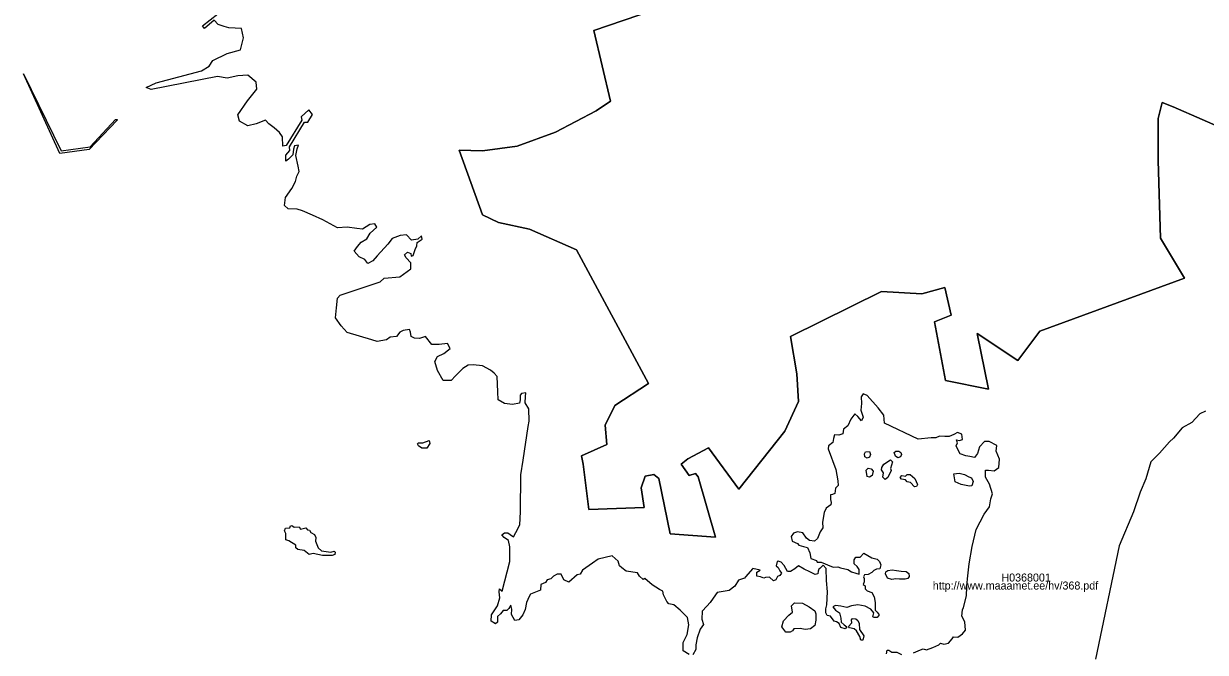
# Model space of a CAD drawing. Extents: x 369010 to 739155, y 6377141 to 6634081.
# Drawn here: x 428377 to 432069, y 6515270 to 6517234 of the extents above; entities that cross this region are included whole.
import ezdxf

# ---------------------------------------------------------------- set-up
doc = ezdxf.new("R2010")
doc.units = 0
for name, color, linetype in [('H_LINK', 7, 'Continuous'), ('H_PIIR', 7, 'Continuous'), ('H_TUNNUS', 7, 'Continuous')]:
    doc.layers.add(name, color=color, linetype=linetype)

msp = doc.modelspace()

# ---------------------------------------------------------------- linework, layer by layer
at = {"layer": 'H_PIIR'}
for points in [[(430456.38, 6515263.5646), (430437.5299, 6515275.0946), (430437.5299, 6515301.2847), (430450.09, 6515326.4346), (430455.3299, 6515356.8247), (430451.14, 6515378.8346), (430428.1, 6515401.8846), (430408.2101, 6515418.6546), (430392.4999, 6515421.7947), (430386.2201, 6515429.1346), (430375.7399, 6515450.0947), (430373.65, 6515461.6247), (430363.1801, 6515466.8647), (430341.1901, 6515481.5346), (430318.1501, 6515501.4447), (430312.9201, 6515498.2946), (430301.4001, 6515508.7746), (430295.1101, 6515519.2546), (430259.51, 6515524.4947), (430245.8999, 6515533.9247), (430238.5701, 6515540.2147), (430234.3799, 6515554.8846), (430215.53, 6515571.6546), (430171.5501, 6515561.1746), (430154.7999, 6515548.5946), (430123.38, 6515527.6346), (430116.0499, 6515515.0646), (430106.63, 6515512.9647), (430080.4501, 6515489.9147), (430064.7399, 6515497.2446), (430056.36, 6515515.0646), (430043.8, 6515515.0646), (430032.28, 6515508.7746), (430023.9001, 6515500.3947), (430012.3801, 6515497.2446), (430007.6699, 6515488.3447), (429993.01, 6515482.0546), (429991.96, 6515464.2346), (429960.55, 6515451.6646), (429956.3601, 6515445.3746), (429947.98, 6515426.5147), (429943.8, 6515404.5047), (429936.47, 6515387.7447), (429923.8999, 6515372.0246), (429911.3401, 6515369.9247), (429900.8599, 6515388.7846), (429901.91, 6515405.5546), (429898.77, 6515418.1346), (429892.49, 6515407.6546), (429887.25, 6515401.3646), (429875.73, 6515401.3646), (429867.3599, 6515390.8846), (429857.93, 6515382.5046), (429857.93, 6515364.6847), (429851.65, 6515359.4446), (429838.0299, 6515367.8346), (429839.08, 6515387.7447), (429857.93, 6515416.0347), (429865.2601, 6515441.1846), (429863.17, 6515459.0046), (429864.21, 6515468.4346), (429872.5899, 6515461.0947), (429895.6299, 6515554.3646), (429895.6299, 6515600.4646), (429891.44, 6515619.3347), (429878.87, 6515628.7646), (429871.5401, 6515637.1447), (429879.92, 6515643.4347), (429890.39, 6515643.4347), (429896.68, 6515638.1947), (429907.15, 6515630.8547), (429914.48, 6515644.4846), (429927.04, 6515668.5846), (429929.1399, 6515709.4546), (429930.18, 6515824.7247), (429937.51, 6515870.8347), (429953.22, 6515975.6246), (429956.3601, 6515992.3946), (429955.32, 6516031.1647), (429943.8, 6516050.0246), (429944.8401, 6516069.9347), (429945.8899, 6516081.4647), (429932.28, 6516079.3646), (429928.0901, 6516074.1246), (429928.0901, 6516059.4547), (429926, 6516048.9747), (429904, 6516044.7846), (429879.92, 6516047.9247), (429860.0201, 6516059.4547), (429858.98, 6516084.6046), (429856.88, 6516131.7646), (429847.46, 6516142.2446), (429835.94, 6516151.6747), (429810.8099, 6516165.2946), (429781.4899, 6516168.4447), (429765.78, 6516167.3947), (429749.03, 6516156.9147), (429735.4101, 6516143.2946), (429725.99, 6516133.8647), (429712.3801, 6516119.1846), (429688.29, 6516119.1846), (429670.49, 6516150.6247), (429662.1101, 6516178.9247), (429670.49, 6516194.6346), (429690.3901, 6516204.0646), (429709.24, 6516219.7847), (429701.9001, 6516235.5047), (429675.73, 6516232.3646), (429652.69, 6516232.3646), (429632.79, 6516257.5146), (429613.94, 6516251.2246), (429598.24, 6516252.2747), (429587.77, 6516257.5146), (429585.67, 6516270.0847), (429582.5301, 6516278.4746), (429562.64, 6516275.3247), (429552.16, 6516270.0847), (429541.69, 6516257.5146), (429522.84, 6516255.4146), (429511.32, 6516247.0347), (429481.9999, 6516241.7947), (429465.2499, 6516247.0347), (429387.76, 6516269.0447), (429368.9099, 6516290.0046), (429351.1101, 6516315.1447), (429354.25, 6516346.5846), (429357.3999, 6516376.9746), (429365.77, 6516386.4046), (429491.43, 6516427.2746), (429504.0001, 6516438.8046), (429552.16, 6516442.9946), (429586.72, 6516468.1446), (429586.72, 6516487.0047), (429572.0601, 6516502.7247), (429566.8199, 6516512.1546), (429576.25, 6516520.5447), (429586.72, 6516516.3447), (429587.77, 6516507.9646), (429594.0501, 6516510.0647), (429600.3299, 6516528.9246), (429605.5701, 6516540.4546), (429606.6199, 6516550.9346), (429622.3201, 6516561.4047), (429620.23, 6516571.8847), (429608.71, 6516561.4047), (429588.8201, 6516558.2646), (429573.1099, 6516575.0346), (429553.21, 6516572.9347), (429528.08, 6516563.5046), (429515.5099, 6516545.6946), (429481.9999, 6516509.0147), (429468.39, 6516493.2947), (429452.6801, 6516484.9146), (429443.26, 6516497.4847), (429425.4599, 6516505.8746), (429409.75, 6516523.6846), (429420.2199, 6516538.3547), (429432.04, 6516551.3846), (429449.54, 6516562.4546), (429460.2401, 6516579.5946), (429480.9601, 6516598.0846), (429474.68, 6516608.5646), (429458.9699, 6516606.4747), (429435.9301, 6516591.8046), (429418.13, 6516593.8946), (429387.76, 6516598.0846), (429357.3999, 6516595.9947), (429312.3699, 6516621.1446), (429279.91, 6516635.8147), (429248.4901, 6516649.4346), (429231.7401, 6516654.6746), (429203.4601, 6516655.7246), (429191.9401, 6516666.2046), (429195.09, 6516691.3547), (429214.9801, 6516719.6447), (429226.5001, 6516741.6546), (429230.69, 6516757.3746), (429238.0201, 6516772.0447), (429234.88, 6516788.8047), (429227.5499, 6516822.3447), (429231.7401, 6516843.3046), (429235.93, 6516854.8246), (429223.36, 6516852.7347), (429220.2201, 6516842.2546), (429218.12, 6516824.4347), (429204.5099, 6516810.8147), (429196.14, 6516804.5246), (429196.14, 6516823.3947), (429208.7, 6516838.0646), (429207.65, 6516849.5846), (429254.7801, 6516926.0847), (429265.25, 6516926.0847), (429279.91, 6516950.1846), (429268.39, 6516964.8647), (429244.2999, 6516942.8547), (429246.4, 6516932.3747), (429197.18, 6516853.7846), (429186.7101, 6516851.6847), (429185.66, 6516881.0247), (429176.83, 6516894.32), (429159.7395, 6516908.8848), (429143.203, 6516920.7911), (429133.2811, 6516932.6973), (429104.1768, 6516921.4525), (429077.7185, 6516914.8379), (429051.9215, 6516929.39), (429046.6299, 6516949.8953), (429076.3955, 6516993.5516), (429105.4998, 6517029.2704), (429104.1768, 6517051.7601), (429077.7185, 6517072.9268), (429046.3899, 6517071.7446), (429013.35, 6517063.73), (428983.33, 6517069.31), (428775.31, 6517028.51), (428760.67, 6517034.47), (428791.9399, 6517049.7446), (428932.8588, 6517086.8174), (428956.6713, 6517101.3695), (428968.9, 6517118.9047), (429012.8954, 6517141.0571), (429054.5674, 6517152.3019), (429063.97, 6517189.58), (429057.9099, 6517219.5046), (429017.91, 6517221.65), (429003.46, 6517225.7946), (428984.6099, 6517232.0746), (428973.0899, 6517244.6547), (428942.72, 6517219.5046), (428936.44, 6517227.8847), (428983.5601, 6517264.5646)], [(432149.14, 6516895.15), (431967.8001, 6516974.8599), (431933.5599, 6516987.79), (431921.16, 6516938.19), (431921.16, 6516806.75), (431928.6, 6516563.71), (432002.9601, 6516439.71), (431551.86, 6516273.55), (431482.4601, 6516181.79), (431356.0499, 6516266.11), (431390.7501, 6516092.51), (431256.9101, 6516119.7899), (431222.2099, 6516303.3099), (431274.2601, 6516323.15), (431254.4299, 6516409.95), (431183.3, 6516390.32), (431057.53, 6516397.9299), (430772.5, 6516256.5699), (430792.3299, 6516140.0099), (430797.33, 6516053.5099), (430755.2, 6515961.8101), (430611.6, 6515780.6601), (430516.22, 6515909.66), (430451.73, 6515875.2701), (430430.99, 6515858.1), (430456.0601, 6515822.7099), (430475.98, 6515829.0499), (430484.51, 6515818.7901), (430538.9799, 6515629.9699), (430397.37, 6515640.86), (430361.05, 6515813.34), (430346.2999, 6515825.82), (430319.3001, 6515820.6), (430306.5901, 6515784.29), (430315.6699, 6515722.56), (430143.1899, 6515717.1199), (430125.03, 6515858.73), (430120.01, 6515884.63), (430199.36, 6515919.4), (430194.0199, 6515980.3701), (430224.0901, 6516041.85), (430328.79, 6516109.9799), (430104.6099, 6516527.3501), (429957.82, 6516592.72), (429860.4699, 6516612.93), (429810.8799, 6516636.8299), (429737.41, 6516838.99), (429810.8799, 6516837.1501), (429919.25, 6516851.85), (430038.59, 6516895.4501), (430165.33, 6516961.6099), (430210.37, 6516992.2199), (430158.1, 6517213.2901), (430345.07, 6517275.91)], [(430345.07, 6517275.91), (430158.1, 6517213.2901), (430210.37, 6516992.2199), (430165.33, 6516961.6099), (430038.59, 6516895.4501), (429919.25, 6516851.85), (429810.8799, 6516837.1501), (429737.41, 6516838.99), (429810.8799, 6516636.8299), (429860.4699, 6516612.93), (429957.82, 6516592.72), (430104.6099, 6516527.3501), (430328.79, 6516109.9799), (430224.0901, 6516041.85), (430194.0199, 6515980.3701), (430199.36, 6515919.4), (430120.01, 6515884.63), (430125.03, 6515858.73), (430143.1899, 6515717.1199), (430315.6699, 6515722.56), (430306.5901, 6515784.29), (430319.3001, 6515820.6), (430346.2999, 6515825.82), (430361.05, 6515813.34), (430397.37, 6515640.86), (430538.9799, 6515629.9699), (430484.51, 6515818.7901), (430475.98, 6515829.0499), (430456.0601, 6515822.7099), (430430.99, 6515858.1), (430451.73, 6515875.2701), (430516.22, 6515909.66), (430611.6, 6515780.6601), (430755.2, 6515961.8101), (430797.33, 6516053.5099), (430792.3299, 6516140.0099), (430772.5, 6516256.5699), (431057.53, 6516397.9299), (431183.3, 6516390.32), (431254.4299, 6516409.95), (431274.2601, 6516323.15), (431222.2099, 6516303.3099), (431256.9101, 6516119.7899), (431390.7501, 6516092.51), (431356.0499, 6516266.11), (431482.4601, 6516181.79), (431551.86, 6516273.55), (432002.9601, 6516439.71), (431928.6, 6516563.71), (431921.16, 6516806.75), (431921.16, 6516938.19), (431933.5599, 6516987.79), (431967.8001, 6516974.8599), (432149.14, 6516895.15)], [(431157.44, 6515269.4146), (431178.3499, 6515278.5646), (431187.4999, 6515281.1847), (431197.9499, 6515278.5646), (431217.5599, 6515285.1047), (431235.85, 6515294.2646), (431241.08, 6515299.4947), (431251.5399, 6515295.5747), (431265.91, 6515299.4947), (431277.6701, 6515312.5746), (431281.5899, 6515319.1147), (431295.9699, 6515317.8046), (431310.35, 6515328.2646), (431319.49, 6515340.0347), (431316.8801, 6515366.1946), (431307.7301, 6515383.1947), (431310.35, 6515402.8147), (431312.96, 6515410.6646), (431322.1101, 6515447.2847), (431323.42, 6515474.7446), (431326.0299, 6515499.5946), (431331.2599, 6515546.6746), (431339.75, 6515600.9546), (431352.82, 6515654.5746), (431377.65, 6515701.6647), (431394.6399, 6515725.2046), (431398.56, 6515750.0546), (431403.79, 6515765.7447), (431394.6399, 6515795.8247), (431381.5701, 6515818.0546), (431381.5701, 6515838.9847), (431390.7201, 6515838.9847), (431409.02, 6515837.6746), (431423.39, 6515848.1346), (431426.0001, 6515874.2947), (431415.5501, 6515899.1447), (431416.86, 6515916.1446), (431393.33, 6515929.2246), (431378.96, 6515929.2246), (431363.28, 6515912.2247), (431356.7401, 6515891.2946), (431347.59, 6515879.5247), (431333.22, 6515882.1446), (431320.1, 6515883.8046), (431302.4701, 6515890.2146), (431295.14, 6515903.8446), (431289.9, 6515915.3646), (431294.09, 6515924.8046), (431290.9501, 6515934.2347), (431300.38, 6515932.1346), (431309.8, 6515935.2846), (431307.7101, 6515952.0447), (431294.09, 6515957.2847), (431282.57, 6515950.9947), (431267.9101, 6515944.7147), (431255.35, 6515944.7147), (431238.59, 6515945.7547), (431227.08, 6515940.5147), (431212.4201, 6515940.5147), (431171.58, 6515936.3246), (431066.86, 6515986.6246), (431064.7701, 6516011.7746), (431046.97, 6516033.7846), (431012.41, 6516072.5546), (430999.84, 6516077.7946), (430993.56, 6516068.3646), (430994.61, 6516047.4047), (430992.5099, 6516026.4446), (430999.84, 6516005.4846), (430994.61, 6515993.9646), (430983.09, 6516007.5847), (430973.6601, 6516015.9646), (430961.1, 6515999.2046), (430951.6801, 6515978.2447), (430938.06, 6515967.7647), (430935.9699, 6515953.0946), (430923.4001, 6515948.9046), (430909.79, 6515949.9547), (430906.6501, 6515938.4247), (430904.55, 6515925.8446), (430891.99, 6515915.3646), (430890.9399, 6515905.9347), (430913.98, 6515842.0147), (430920.26, 6515806.3846), (430921.31, 6515791.7147), (430912.9299, 6515783.3346), (430910.84, 6515766.5646), (430903.51, 6515763.4247), (430897.22, 6515762.3747), (430897.22, 6515747.7046), (430899.32, 6515738.2746), (430898.27, 6515730.9346), (430884.6599, 6515720.4546), (430878.3801, 6515706.8347), (430873.1399, 6515677.4947), (430874.1899, 6515659.6747), (430865.81, 6515647.1046), (430857.43, 6515626.1447), (430848.01, 6515617.7646), (430832.3001, 6515619.8547), (430822.3499, 6515626.6647), (430810.8299, 6515643.4347), (430795.13, 6515646.5746), (430782.5599, 6515642.3847), (430775.23, 6515631.9047), (430778.37, 6515617.2346), (430795.13, 6515610.9446), (430799.3201, 6515605.7046), (430812.93, 6515601.5146), (430825.49, 6515598.3747), (430832.8201, 6515581.6046), (430835.97, 6515563.7947), (430853.77, 6515557.5047), (430855.8601, 6515552.2647), (430868.4299, 6515552.2647), (430900.8901, 6515538.6446), (430907.1699, 6515536.5446), (430920.78, 6515537.5946), (430929.1601, 6515534.4547), (430952.2001, 6515529.2147), (430963.7199, 6515521.8746), (430977.33, 6515517.6847), (430986.7599, 6515514.5446), (430986.7599, 6515529.2147), (430981.5199, 6515538.6446), (430972.1, 6515547.0247), (430972.1, 6515559.6046), (430977.33, 6515567.9847), (430989.9, 6515567.9847), (431001.42, 6515580.5547), (431026.5499, 6515565.8846), (431043.2999, 6515561.6946), (431050.63, 6515554.3646), (431054.8199, 6515543.8846), (431051.68, 6515531.3046), (431041.21, 6515530.2546), (431032.83, 6515526.0646), (431026.5499, 6515519.7846), (431015.0299, 6515513.4946), (431003.5099, 6515512.4447), (431000.37, 6515506.1547), (431002.4601, 6515500.9147), (431002.4601, 6515490.4346), (430999.32, 6515482.0546), (431005.6, 6515477.8647), (431005.6, 6515468.4346), (431011.89, 6515462.1446), (431026.5499, 6515456.9046), (431033.88, 6515444.3247), (431037.0201, 6515426.5147), (431037.0201, 6515412.8946), (431037.0201, 6515402.4147), (431043.2999, 6515396.1246), (431049.58, 6515387.7447), (431043.2999, 6515379.3546), (431033.88, 6515379.3546), (431029.69, 6515381.4547), (431032.83, 6515394.0246), (431023.4, 6515405.5546), (431005.6, 6515414.9847), (430983.61, 6515419.1846), (430963.7199, 6515416.0347), (430949.06, 6515410.7946), (430930.2099, 6515414.9847), (430913.4599, 6515417.0846), (430905.08, 6515412.8946), (430913.4599, 6515402.4147), (430926.02, 6515394.0246), (430930.2099, 6515377.2646), (430931.26, 6515364.6847), (430940.6801, 6515356.3046), (430949.06, 6515350.0146), (430943.82, 6515343.7246), (430930.2099, 6515347.9246), (430924.9699, 6515360.4946), (430916.6, 6515365.7346), (430909.27, 6515367.8346), (430897.75, 6515383.5546), (430887.28, 6515385.6447), (430883.09, 6515394.0246), (430883.09, 6515406.6046), (430886.23, 6515419.1846), (430888.32, 6515459.0046), (430885.1799, 6515494.6247), (430884.1301, 6515532.3546), (430874.71, 6515542.8346), (430864.24, 6515532.3546), (430861.1001, 6515530.2546), (430859, 6515523.9747), (430857.96, 6515515.5846), (430849.5801, 6515513.4946), (430832.8201, 6515521.8746), (430815.02, 6515530.2546), (430798.27, 6515540.7347), (430786.75, 6515531.3046), (430773.14, 6515522.9247), (430763.71, 6515522.9247), (430753.2401, 6515541.7846), (430743.8199, 6515552.2647), (430734.39, 6515555.4046), (430731.2501, 6515554.3646), (430728.11, 6515540.7347), (430734.39, 6515535.4947), (430739.63, 6515525.0246), (430744.86, 6515517.6847), (430739.63, 6515510.3446), (430732.2999, 6515507.2047), (430727.0599, 6515496.7246), (430719.7301, 6515493.5847), (430707.17, 6515505.1047), (430694.6, 6515504.0646), (430689.36, 6515501.9646), (430678.89, 6515506.1547), (430667.38, 6515508.2546), (430667.38, 6515520.8246), (430677.85, 6515527.1146), (430654.81, 6515532.3546), (430631.77, 6515506.1547), (430628.6301, 6515501.9646), (430610.83, 6515495.6747), (430599.31, 6515476.8147), (430581.51, 6515463.1946), (430543.8101, 6515456.9046), (430531.25, 6515440.1346), (430521.8201, 6515426.5147), (430511.3499, 6515414.9847), (430496.69, 6515399.2646), (430495.64, 6515374.1147), (430500.8799, 6515357.3547), (430490.41, 6515342.6846), (430480.98, 6515315.4346), (430476.7901, 6515293.4246), (430476.7901, 6515279.8046), (430467.89, 6515262.5146)], [(432069.3234, 6516023.6155), (432051.0235, 6516015.7655), (432026.1935, 6515988.2954), (431996.1433, 6515971.2955), (431968.6934, 6515939.9054), (431956.9333, 6515928.1354), (431924.9134, 6515892.1755), (431898.7735, 6515866.0154), (431883.0935, 6515812.3954), (431864.7934, 6515770.5455), (431843.8835, 6515709.0754), (431799.4535, 6515603.1355), (431725.3051, 6515248.8625)], [(431072.49, 6515265.4947), (431075.1101, 6515277.2646), (431080.3301, 6515277.2646), (431089.4799, 6515270.7247), (431105.1601, 6515270.7247), (431119.5401, 6515264.1846)]]:
    msp.add_lwpolyline(points, dxfattribs=at)
for points in [[(428377.4834, 6517077.9274), (428494.9912, 6516836.6226), (428585.1908, 6516849.5319), (428664.3019, 6516935.263), (428670.0944, 6516935.263), (428670.0944, 6516932.615), (428581.8808, 6516841.0911), (428491.0192, 6516828.1819)], [(429643.92, 6515931.8123), (429646.4025, 6515922.7095), (429636.6379, 6515908.1451), (429621.577, 6515907.8141), (429610.4883, 6515915.0963), (429607.3437, 6515922.0475), (429610.8192, 6515925.1921), (429624.7216, 6515924.8611)], [(431019.4238, 6515880.175), (431011.976, 6515876.8649), (431005.1903, 6515881.6645), (431003.7009, 6515890.9328), (431007.3419, 6515897.222), (431019.5893, 6515898.2149), (431022.8993, 6515887.9537)], [(431116.5746, 6515881.0025), (431108.4649, 6515877.8579), (431100.3551, 6515882.9886), (431097.0451, 6515894.2429), (431101.3481, 6515899.0425), (431111.4439, 6515898.877), (431117.4021, 6515895.0704), (431119.7192, 6515888.7812)], [(431077.0192, 6515816.125), (431068.9093, 6515810.8288), (431061.4617, 6515817.78), (431062.9513, 6515831.5168), (431056.9931, 6515840.2885), (431057.6551, 6515847.9017), (431064.7718, 6515858.6595), (431084.7977, 6515871.7342), (431091.2525, 6515865.9417), (431085.2943, 6515844.2606), (431087.1148, 6515838.3025)], [(431027.5334, 6515823.2417), (431019.0927, 6515817.4489), (431012.307, 6515819.435), (431009.1624, 6515839.9575), (431015.1206, 6515845.9157), (431025.2164, 6515843.7641), (431031.3401, 6515836.482)], [(431146.5308, 6515826.0551), (431160.7641, 6515812.9804), (431169.3704, 6515795.1059), (431166.5567, 6515787.9893), (431160.2676, 6515787.4927), (431147.1929, 6515800.8985), (431137.0971, 6515802.8846), (431131.8009, 6515809.6704), (431119.8846, 6515810.9943), (431115.5816, 6515816.787), (431120.3812, 6515822.5796), (431131.8009, 6515820.7591), (431137.5935, 6515826.0551)], [(431287.2636, 6515802.9335), (431282.5011, 6515827.5398), (431299.9637, 6515829.9211), (431316.6325, 6515825.9523), (431329.3325, 6515818.8086), (431338.0637, 6515815.6336), (431343.62, 6515804.521), (431339.6513, 6515790.2335), (431331.7137, 6515789.4398), (431306.3137, 6515794.996)], [(429215.2646, 6515666.6748), (429222.3813, 6515661.3786), (429237.6076, 6515662.2062), (429242.4072, 6515655.5861), (429258.7921, 6515659.5582), (429264.5849, 6515652.9381), (429270.3775, 6515652.276), (429274.3496, 6515644.4973), (429285.9349, 6515638.7047), (429290.569, 6515629.6019), (429289.2449, 6515617.3546), (429297.0237, 6515596.5011), (429308.1124, 6515587.3983), (429336.5791, 6515583.5919), (429347.0058, 6515586.2399), (429350.8124, 6515583.5919), (429348.9919, 6515575.8132), (429341.0477, 6515572.5031), (429310.5949, 6515573.165), (429282.1283, 6515579.6198), (429269.0534, 6515575.8132), (429253.4961, 6515588.7224), (429234.1321, 6515591.3706), (429228.1739, 6515596.5011), (429228.1739, 6515604.9419), (429206.1618, 6515619.1752), (429196.3972, 6515621.8232), (429196.3972, 6515641.3527), (429192.5905, 6515650.4554), (429195.7351, 6515658.2341), (429208.81, 6515658.8961), (429210.6305, 6515666.0128)], [(431143.8592, 6515507.3934), (431138.8321, 6515501.3079), (431131.4238, 6515499.1913), (431113.6462, 6515498.8703), (431102.0224, 6515499.8713), (431088.8258, 6515498.1329), (431076.1257, 6515502.1017), (431069.5714, 6515515.5696), (431070.3989, 6515522.0244), (431076.5226, 6515526.4929), (431090.6778, 6515528.5601), (431103.907, 6515525.9142), (431118.5094, 6515524.2343), (431133.805, 6515522.4746), (431142.2717, 6515516.6538)], [(430779.1277, 6515395.6599), (430775.4235, 6515415.2391), (430785.4777, 6515424.7642), (430810.3486, 6515423.9704), (430831.5153, 6515412.8579), (430848.7133, 6515399.6287), (430851.8883, 6515390.8974), (430851.6237, 6515371.0536), (430849.2424, 6515354.6494), (430834.9549, 6515343.5369), (430818.8153, 6515341.4202), (430802.9402, 6515345.1244), (430783.0965, 6515343.8015), (430779.3923, 6515337.1869), (430771.4548, 6515333.4827), (430758.2256, 6515333.2181), (430745.5255, 6515350.4161), (430751.0818, 6515369.2015), (430768.0152, 6515386.6641)], [(430998.5702, 6515308.1932), (430992.4465, 6515308.0277), (430989.7985, 6515320.2749), (430979.3718, 6515337.8184), (430971.924, 6515344.1076), (430957.1943, 6515347.4176), (430954.0497, 6515350.8932), (430964.4764, 6515362.4785), (430963.4834, 6515371.9122), (430965.966, 6515376.2152), (430976.7236, 6515375.5534), (430983.0128, 6515370.4227), (430987.4814, 6515360.4925), (430988.6399, 6515342.1215), (431001.7148, 6515322.261)]]:
    msp.add_lwpolyline(points, close=True, dxfattribs=at)

# ---------------------------------------------------------------- texts
at = {"layer": 'H_LINK'}
msp.add_text('http://www.maaamet.ee/hv/368.pdf', height=25, rotation=0, dxfattribs=at).set_placement((431217.2555, 6515466.6291))
at = {"layer": 'H_TUNNUS'}
msp.add_text('H0368001', height=25, rotation=0, dxfattribs=at).set_placement((431431.6095, 6515491.6291))

doc.saveas('drawing.dxf')
